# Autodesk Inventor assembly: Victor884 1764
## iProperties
Shininess: 64.0
Length Units: 11272
Angle Units: 11279
Time Units: 11290
Mass Units: 11286
Length Display Precision: 3
Angle Display Precision: 2
Compacted: True
Part Number: Victor884 1764
Document SubType Name: Assembly
Created: 2007-01
Designer: uidk0133
Density: 0.0
Volumn: 0.0
Area: 0.0
PropertySet Name: Model Information
Control State: 0
Master: False
Checked Out: False
Author: uidk0133
